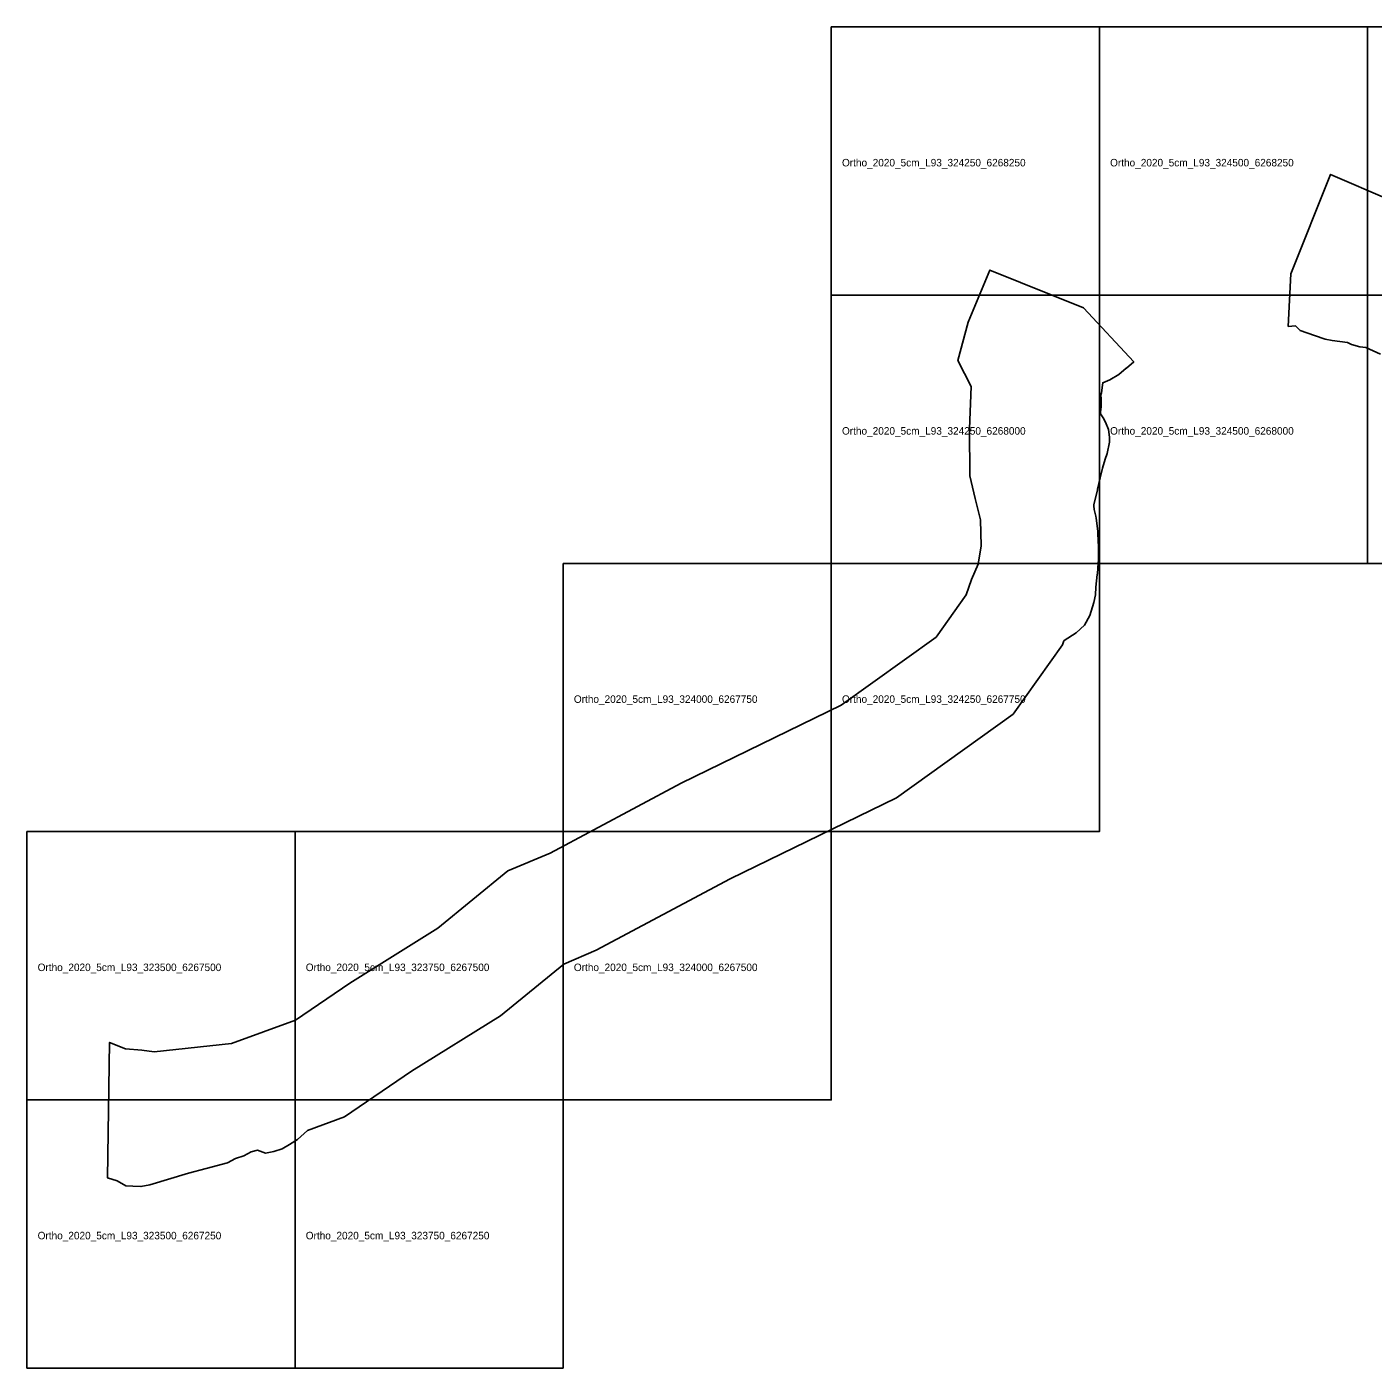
# Model space of a CAD drawing. Extents: x 322000 to 326000, y 6266750 to 6269250.
# Drawn here: x 323500 to 324755, y 6267000 to 6268250 of the extents above; entities that cross this region are included whole.
import ezdxf

# ---------------------------------------------------------------- set-up
doc = ezdxf.new("R2010")
doc.units = 0
for name, color, linetype in [('Ortho_footprint', 7, 'Continuous'), ('Ortho_name', 7, 'Continuous'), ('Perim', 7, 'Continuous')]:
    doc.layers.add(name, color=color, linetype=linetype)

msp = doc.modelspace()

# ---------------------------------------------------------------- linework, layer by layer
at = {"layer": 'Ortho_footprint'}
for points in [[(324250, 6268250), (324500, 6268250), (324500, 6268000), (324250, 6268000)], [(324500, 6268250), (324750, 6268250), (324750, 6268000), (324500, 6268000)], [(324750, 6268250), (325000, 6268250), (325000, 6268000), (324750, 6268000)], [(324250, 6268000), (324500, 6268000), (324500, 6267750), (324250, 6267750)], [(324500, 6268000), (324750, 6268000), (324750, 6267750), (324500, 6267750)], [(324750, 6268000), (325000, 6268000), (325000, 6267750), (324750, 6267750)], [(324000, 6267750), (324250, 6267750), (324250, 6267500), (324000, 6267500)], [(324250, 6267750), (324500, 6267750), (324500, 6267500), (324250, 6267500)], [(323500, 6267500), (323750, 6267500), (323750, 6267250), (323500, 6267250)], [(323750, 6267500), (324000, 6267500), (324000, 6267250), (323750, 6267250)], [(324000, 6267500), (324250, 6267500), (324250, 6267250), (324000, 6267250)], [(323500, 6267250), (323750, 6267250), (323750, 6267000), (323500, 6267000)], [(323750, 6267250), (324000, 6267250), (324000, 6267000), (323750, 6267000)]]:
    msp.add_lwpolyline(points, close=True, dxfattribs=at)
at = {"layer": 'Perim'}
msp.add_lwpolyline([(324770.5, 6268088.9), (324715.6, 6268112.5), (324678.5, 6268019.8), (324676.1, 6267970.9), (324682.9, 6267971.3), (324687.1, 6267967.2), (324700.7, 6267962.4), (324710.4, 6267959.1), (324717.2, 6267957.6), (324731.3, 6267956), (324735.1, 6267954), (324742.8, 6267951.8), (324748.4, 6267951.1), (324762, 6267944.9)], dxfattribs=at)
msp.add_lwpolyline([(324485.1, 6267988.3), (324532.1, 6267937.8), (324525.3, 6267932), (324525, 6267931.8), (324518.1, 6267925.9), (324509.9, 6267921), (324503.1, 6267918.3), (324503, 6267916.1), (324501.9, 6267909.1), (324501.4, 6267907.2), (324501.3, 6267906.2), (324501.7, 6267903.9), (324501.7, 6267896.1), (324501.1, 6267890.8), (324501.2, 6267889.5), (324501.2, 6267889.5), (324503.5, 6267885.8), (324505.7, 6267881.7), (324508.4, 6267874.9), (324509.3, 6267867.6), (324509.3, 6267862.9), (324507.3, 6267852.4), (324505.3, 6267847), (324503, 6267838.6), (324500.7, 6267829.8), (324498.4, 6267819.1), (324498.2, 6267818.2), (324494.8, 6267804.8), (324494.7, 6267804), (324494.7, 6267803.7), (324495.3, 6267800.1), (324496.6, 6267793.9), (324496.9, 6267792.1), (324498.2, 6267782.5), (324498.5, 6267779.8), (324499, 6267769.1), (324499.1, 6267767.5), (324499.1, 6267753), (324499, 6267750.5), (324498.2, 6267740.4), (324498.1, 6267739.5), (324496.8, 6267727.7), (324496.3, 6267720.6), (324494.9, 6267713.6), (324491.1, 6267701.5), (324486.2, 6267692.3), (324478.4, 6267685.2), (324467.1, 6267678.1), (324466.8, 6267677.9), (324465.5, 6267674.1), (324419.6, 6267609.6), (324310.7, 6267531.6), (324155.8, 6267456.1), (324030.9, 6267389.4), (324000.6, 6267376.6), (323941.5, 6267328.3), (323858.5, 6267276.7), (323796, 6267234.3), (323761.6, 6267221.4), (323752.4, 6267213), (323744.7, 6267208.5), (323738.1, 6267204.3), (323730.3, 6267201.7), (323722.4, 6267200.4), (323714.9, 6267203), (323709.2, 6267201.4), (323702.2, 6267197.8), (323694.5, 6267195.2), (323687.1, 6267191.3), (323667.2, 6267186.1), (323650.7, 6267181.8), (323614.7, 6267170.8), (323606.3, 6267169.1), (323598.9, 6267169.6), (323592.3, 6267170), (323584.1, 6267174.4), (323575.2, 6267177.3), (323577.1, 6267303.5), (323591.8, 6267297.4), (323607.2, 6267296.4), (323618.5, 6267294.8), (323690.8, 6267302.5), (323750.4, 6267324.2), (323801, 6267358.7), (323803.5, 6267360.4), (323883.2, 6267410), (323948.5, 6267463.3), (323987.8, 6267479.8), (324110.2, 6267545.1), (324259.3, 6267618), (324347.8, 6267681.2), (324375.9, 6267720.7), (324380.9, 6267735.1), (324386.9, 6267749.3), (324389.8, 6267766.4), (324389.3, 6267790.7), (324384.2, 6267810.4), (324379.3, 6267831.7), (324379, 6267875.3), (324380.6, 6267914.8), (324368, 6267939.2), (324377.8, 6267974.8), (324397.9, 6268023.4)], close=True, dxfattribs=at)

# ---------------------------------------------------------------- texts
at = {"layer": 'Ortho_name'}
for s, p in [('Ortho_2020_5cm_L93_324250_6268250', (324260, 6268120)), ('Ortho_2020_5cm_L93_324500_6268250', (324510, 6268120)), ('Ortho_2020_5cm_L93_324250_6268000', (324260, 6267870)), ('Ortho_2020_5cm_L93_324500_6268000', (324510, 6267870)), ('Ortho_2020_5cm_L93_324000_6267750', (324010, 6267620)), ('Ortho_2020_5cm_L93_324250_6267750', (324260, 6267620)), ('Ortho_2020_5cm_L93_323500_6267500', (323510, 6267370)), ('Ortho_2020_5cm_L93_323750_6267500', (323760, 6267370)), ('Ortho_2020_5cm_L93_324000_6267500', (324010, 6267370)), ('Ortho_2020_5cm_L93_323500_6267250', (323510, 6267120)), ('Ortho_2020_5cm_L93_323750_6267250', (323760, 6267120))]:
    msp.add_text(s, height=7, dxfattribs=at).set_placement(p)

doc.saveas('drawing.dxf')
